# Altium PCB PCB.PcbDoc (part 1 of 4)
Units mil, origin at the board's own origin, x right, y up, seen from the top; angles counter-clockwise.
Board outline 6311.26 x 4737.49 mil, 2 copper layers (Top Layer, Bottom Layer); 252 components, 238 nets, 1140 pads, 635 vias.
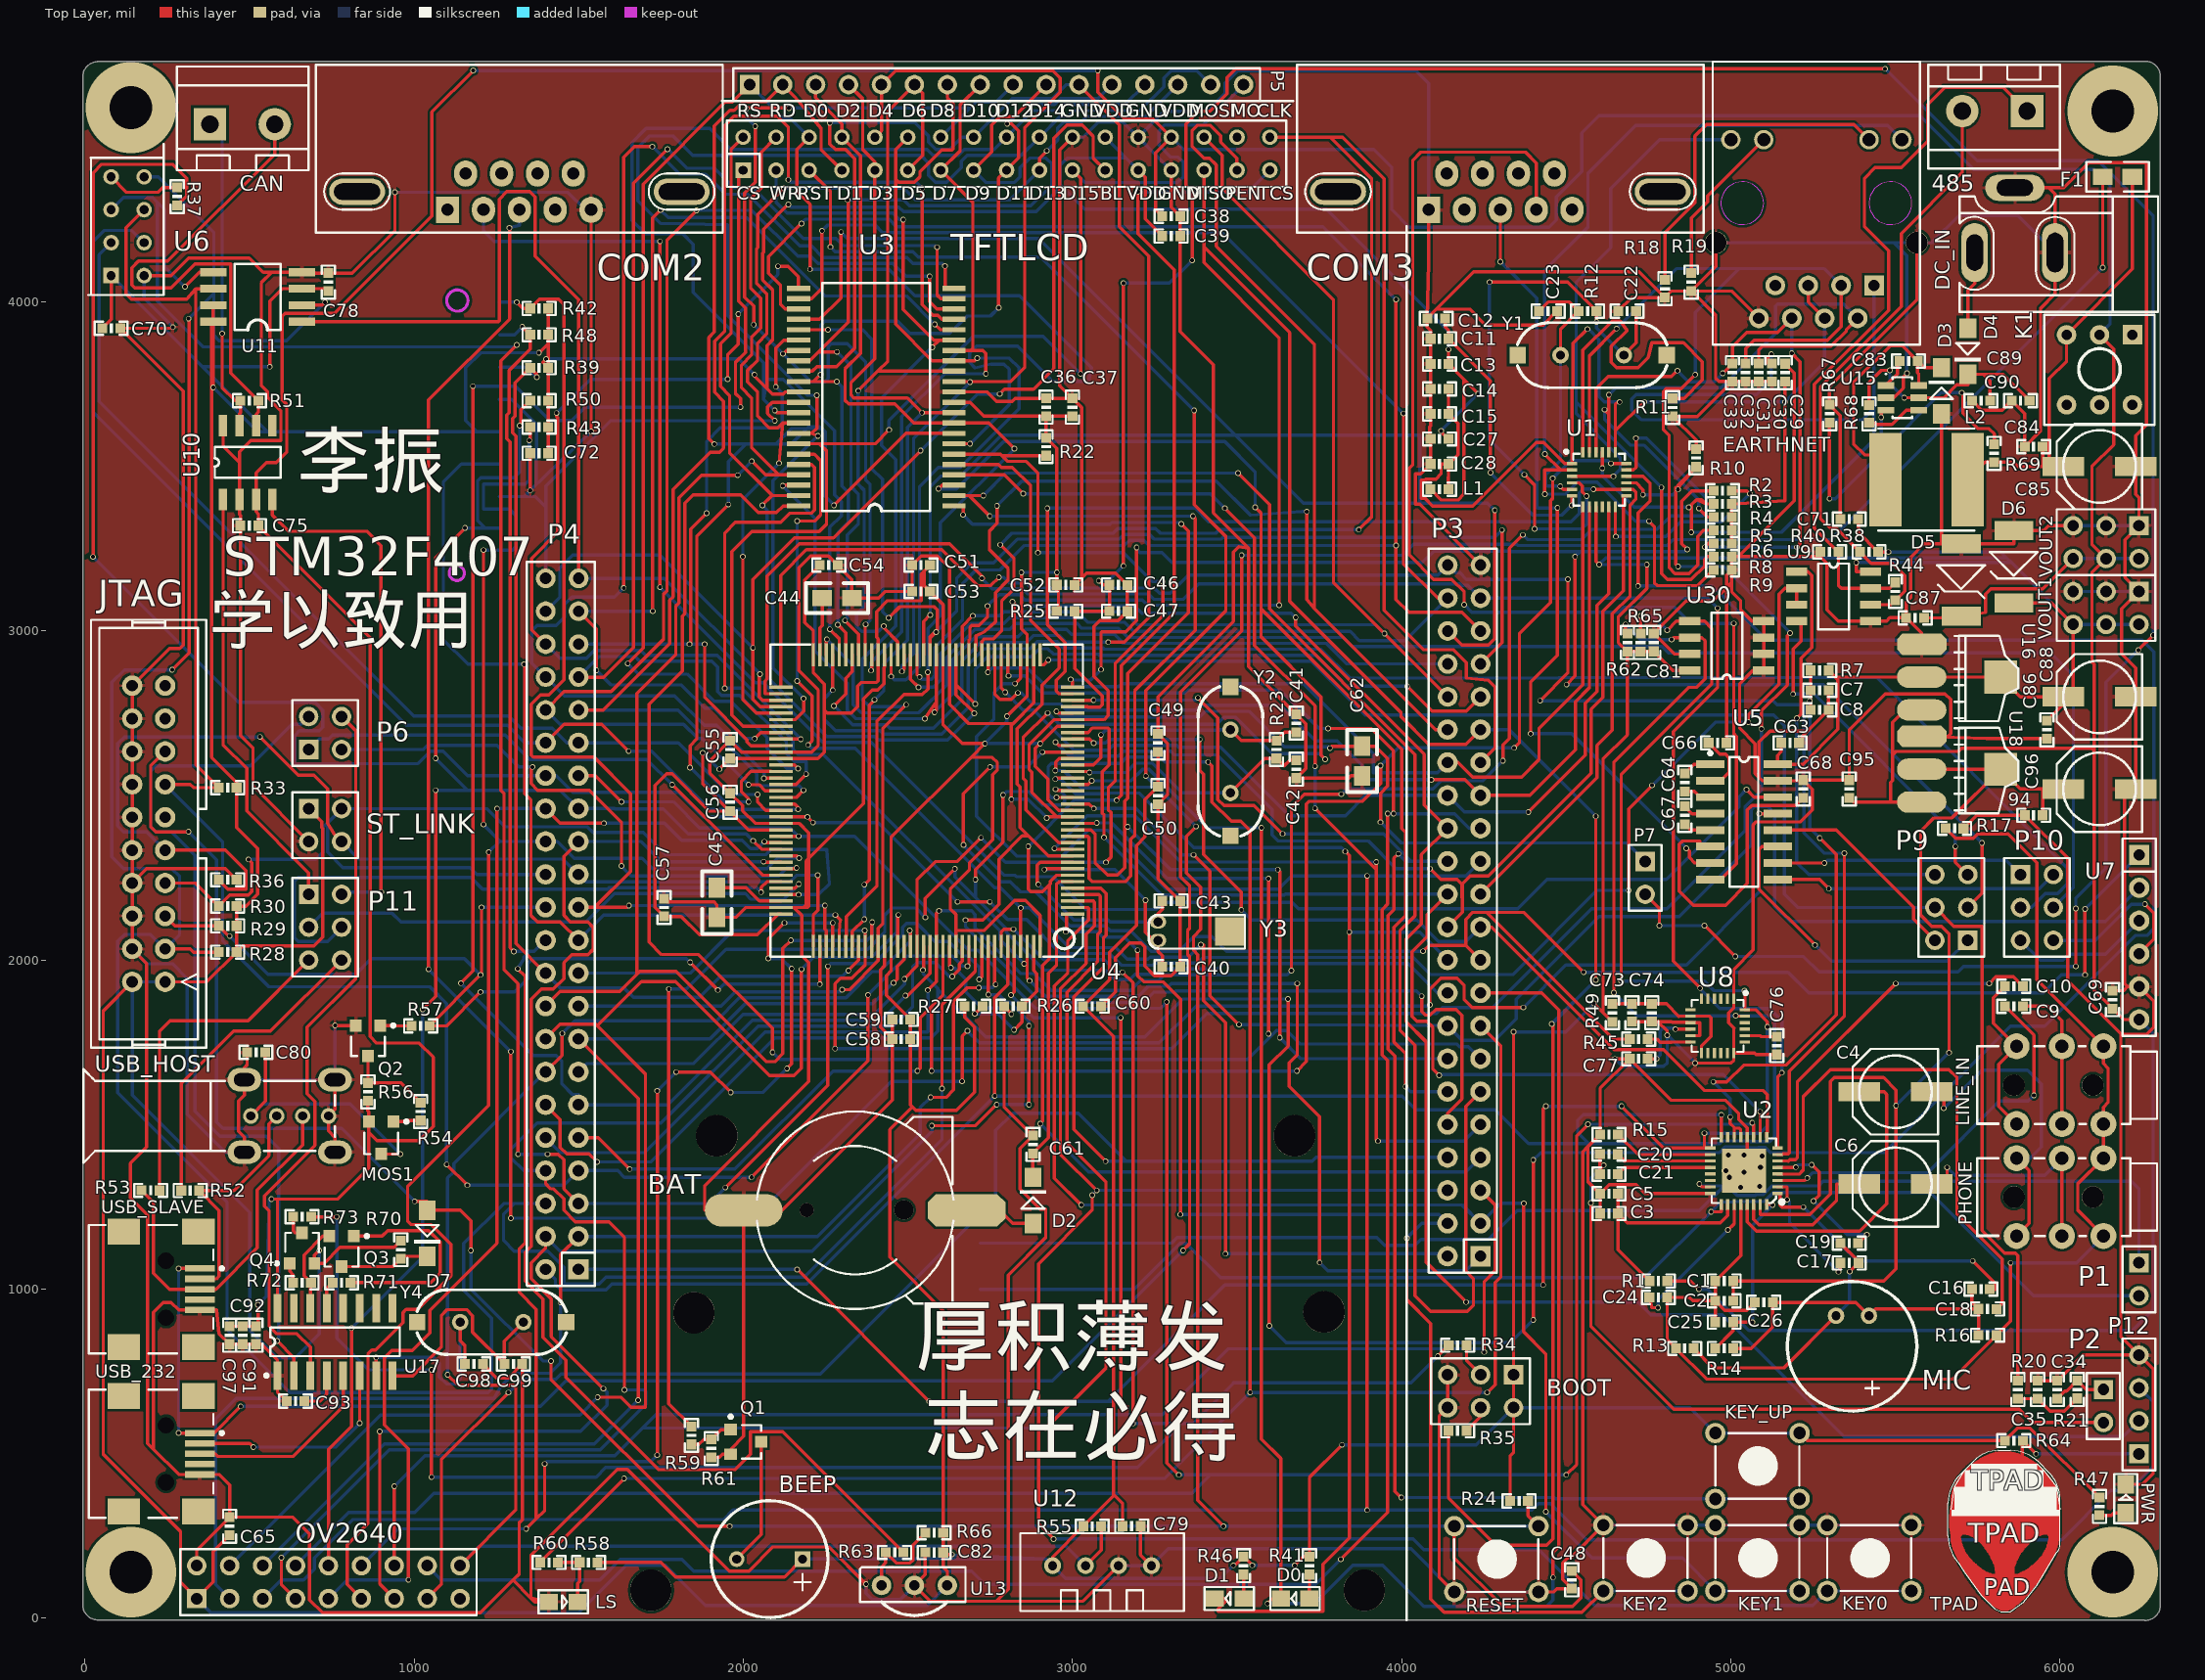
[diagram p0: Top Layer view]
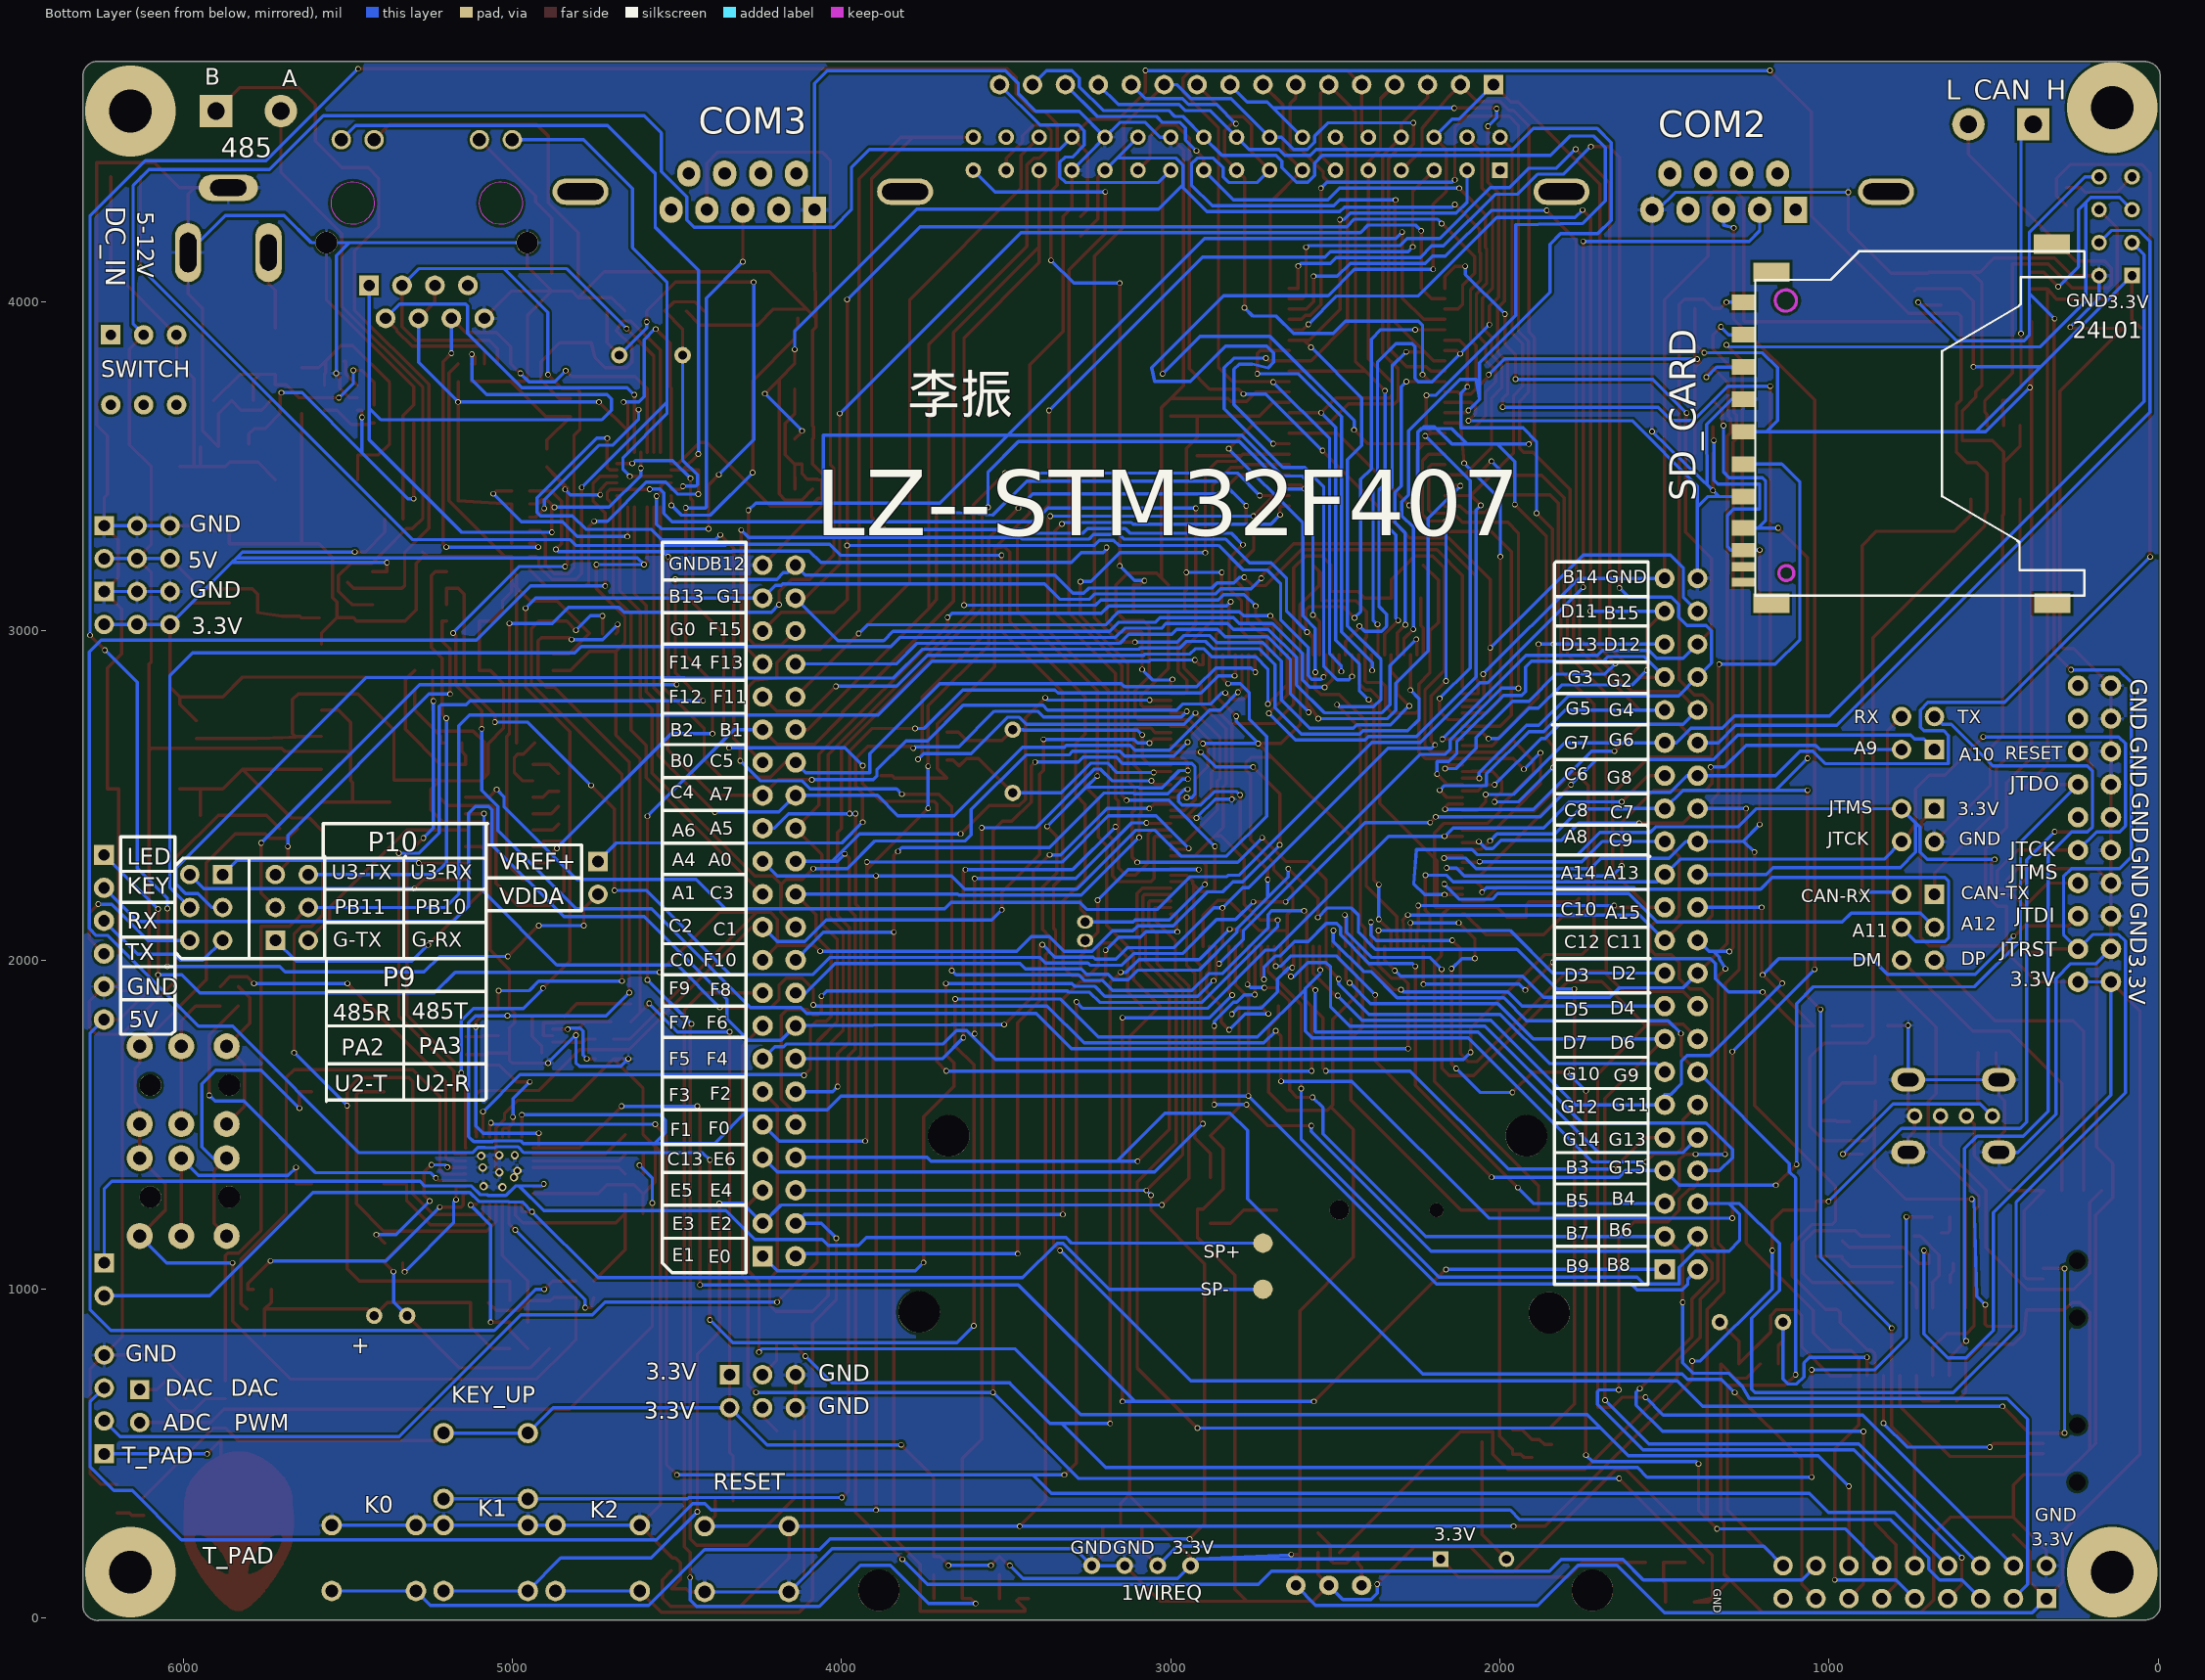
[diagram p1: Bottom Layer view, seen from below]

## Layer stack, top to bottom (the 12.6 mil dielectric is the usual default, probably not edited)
Top Layer: signal copper 1.4
Dielectric: dielectric 12.6, FR-4, Dk 4.8
Bottom Layer: signal copper 1.4

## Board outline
40,-5.01 cw(c40,41.23) -6.25,41.23 -6.25,4683.77 cw(c40,4683.77) 37.89,4729.97 cw(c41.23,4726.23) 41.23,4731.25 6258.77,4731.25 cw(c6258.77,4685) 6305.02,4685 6305.02,40 cw(c6258.77,40) 6258.77,-6.25 cw(c6258.77,-1.23) 6255.48,-5.01

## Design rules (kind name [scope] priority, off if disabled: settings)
Clearance [All] p1: gap=8
FabricationTestpoint [All] p1: side=3 testpointundercomponent=TRUE minsize=40 maxsize=1000 preferedsize=60 minholesize=0 maxholesize=400 preferedholesize=32 testpointgrid=1 allowsidetop=TRUE allowsidebottom=TRUE usegrid=TRUE gridtolerance=0.01
HoleSize [All] p1: absolutevalues=TRUE maxlimit=1000 minlimit=8 maxpercent=80.000 minpercent=20.000
HoleToHoleClearance [All] p1: gap=0 allowstackedmicrovias=TRUE
MinimumSolderMaskSliver [All] p1: minsoldermaskwidth=0
PasteMaskExpansion [All] p1: expansion=10
PlaneClearance [All] p1: clearance=10
PolygonConnect [All] p1: connectstyle=Relief reliefconductorwidth=10 reliefentries=4 polygonreliefangle="90 Angle"
RoutingVias [All] p1: holewidth=12 width=17 viastyle="Through Hole" minholewidth=10 minwidth=17 maxholewidth=1000 maxwidth=1000
SMDNeckDown [All] p1: percent=100.000
SilkToSilkClearance [All] p1: silktosilkclearance=0
SilkscreenOverComponentPads [All] p1: minsilkscreentomaskgap=0
SolderMaskExpansion [All] p1: expansion=10
Width [All] p1: maxlimit=15 minlimit=5 preferedwidth=10
20 further rules are at their usual default settings.

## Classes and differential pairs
component class CPU2: BAT BOOT C36 C37 C38 C39 C40 C41 C42 C43 C44 C45 C46 C47 C48 C49 C50 C51 C52 C53 C54 C55 C56 C57 C58 C59 C60 C61 C62 D2 JTAG P3 P4 P5 P6 P7 R22 R23 R24 R25 R26 R27 R28 R29 R30 R33 R34 R35 R36 RESET ST_LINK TFTLCD U3 U4 Y2 Y3
component class CPU3: BEEP C63 C64 C65 C66 C67 C68 C69 C70 C71 C72 C73 C74 C75 C76 C77 C78 C79 C80 C81 C82 CAN COM2 COM3 D0 D1 KEY0 KEY1 KEY2 KEY_UP LS MOS1 OV2640 P9 P10 P11 P12 PWR Q1 Q2 R37 R38 R39 R40 R41 R42 R43 R44 R45 R46 R47 R48 R49 R50 R51 R52 R53 R54 R55 R56 R57 R58 R59 R60 R61 R62 R63 R64 R65 R66 RS485 SD_CARD TPAD U5 U6 U7 U8 U9 U10 U11 U12 U13 U30 USB_HOST USB_SLAVE
component class PCU1: 94 C1 C2 C3 C4 C5 C6 C7 C8 C9 C10 C11 C12 C13 C14 C15 C16 C17 C18 C19 C20 C21 C22 C23 C24 C25 C26 C27 C28 C29 C30 C31 C32 C33 C34 C35 C83 C84 C85 C86 C87 C88 C89 C90 C91 C92 C93 C95 C96 C97 C98 C99 D3 D4 D5 D6 D7 DC_IN EARTHNET F1 K1 L1 L2 LINE_IN MIC P1 P2 PHONE Q3 Q4 R1 R2 R3 R4 R5 R6 R7 R8 R9 R10 R11 R12 R13 R14 R15 R16 R17 R18 R19 R20 R21 R67 R68 R69 R70 R71 R72 R73 SP+ SP- U1 U2 U15 U16 U17 U18 USB_232 VOUT1 VOUT2 Y1 Y4

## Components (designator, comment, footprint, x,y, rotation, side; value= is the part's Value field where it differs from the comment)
94 "104pF" 0603P 5920,2440 r0 top
485 "RS485" HEAD2L-0.8 5900,4580 r180 top (schematic designator RS485)
BAT "BATT" BATM 2340,1240 r90 top
BEEP "BEEP" BELL-5 2180,180 r180 top
BOOT "BOOT" HDR2X3 4340,740 r180 top
C1 "104pF" 0603P 4980,1025 r0 top
C2 "10uF" 0603P 4980,965 r0 top
C3 "10uF" 0603P 4630,1230 r0 top
C4 "220uF" CC6.56.5 5500,1600 r0 top
C5 "104pF" 0603P 4630,1290 r0 top
C6 "220uF" CC6.56.5 5500,1320 r0 top
C7 "104pF" 0603P 5270,2820 r180 top
C8 "10uF" 0603P 5270,2760 r180 top
C9 "1uF" 0603P 5860,1860 r0 top
C10 "1uF" 0603P 5860,1920 r180 top
C11 "104pF" 0603P 4115,3887.88 r0 top
C12 "10uF" 0603P 4105,3950 r0 top
C13 "104pF" 0603P 4115,3811.75 r0 top
C14 "104pF" 0603P 4115,3735.63 r0 top
C15 "104pF" 0603P 4115,3659.5 r0 top
C16 "1uF" 0603P 5760,1000 r180 top
C17 "1uF" 0603P 5360,1080 r0 top
C18 "1uF" 0603P 5780,940 r180 top
C19 "1uF" 0603P 5360,1140 r180 top
C20 "104pF" 0603P 4630,1410 r180 top
C21 "104pF" 0603P 4630,1350 r180 top
C22 "22pF" 0603P 4685,3972 r0 top
C23 "22pF" 0603P 4445,3972 r180 top
C24 "10uF" 0603P 4780,975 r180 top
C25 "10uF" 0603P 4980,900 r0 top
C26 "221pF" 0603P 5100,960 r0 top
C27 "104pF" 0603P 4115,3583.38 r0 top
C28 "10uF" 0603P 4115,3507.25 r0 top
C29 "223pF" 0603P 5164.94,3785 r270 top
C30 "10pF" 0603P 5124.94,3785 r90 top
C31 "10pF" 0603P 5084.94,3785 r90 top
C32 "10pF" 0603P 5044.94,3785 r90 top
C33 "10pF" 0603P 5004.94,3785 r90 top
C34 "102pF" 0603P 5932,695 r270 top
C35 "101pF" 0603P 5992,695 r270 top
C36 "104pF" 0603P 2920,3680 r270 top
C37 "104pF" 0603P 3000,3680 r270 top
C38 "104pF" 0603P 3300,4260 r0 top
C39 "104pF" 0603P 3300,4200 r0 top
C40 "10pF" 0603P 3300,1980 r0 top
C41 "22pF" 0603P 3680,2720 r270 top
C42 "22pF" 0603P 3680,2580 r90 top
C43 "10pF" 0603P 3300,2180 r0 top
C44 "225pF" 0805 2240,3100 r0 top
C45 "225pF" 0805 1920,2220 r270 top
C46 "10uF" 0603P 3140,3140 r180 top
C47 "104pF" 0603P 3140,3060 r180 top
C48 "104pF" 0603P 4517,117 r90 top
C49 "104" 0603P 3260,2660 r270 top
C50 "104" 0603P 3260,2500 r90 top
C51 "104" 0603P 2540,3200 r0 top
C52 "104" 0603P 2980,3140 r180 top
C53 "104" 0603P 2540,3120 r0 top
C54 "104" 0603P 2260,3200 r180 top
C55 "104" 0603P 1960,2640 r270 top
C56 "104" 0603P 1960,2480 r270 top
C57 "104" 0603P 1760,2160 r270 top
C58 "104" 0603P 2480,1760 r0 top
C59 "104" 0603P 2480,1820 r0 top
C60 "104" 0603P 3060,1860 r180 top
C61 "104pF" 0603P 2880,1440 r270 top
C62 "225pF" 0805 3880,2560 r90 top
C63 "104pF" 0603P 5180,2660 r0 top
C64 "104pF" 0603P 4860,2540 r270 top
C65 "104pF" 0603P 440,280 r90 top
C66 "104pF" 0603P 4960,2660 r180 top
C67 "104pF" 0603P 4860,2440 r90 top
C68 "104pF" 0603P 5220,2520 r270 top
C69 "104pF" 0603P 6160,1880 r270 top
C70 "104pF" 0603P 80,3920 r0 top
C71 "104pF" 0603P 5360,3340 r180 top
C72 "104pF" 0603P 1380,3540 r0 top
C73 "10uF" 0603P 4700,1840 r90 top
C74 "104pF" 0603P 4760,1840 r90 top
C75 "104pF" 0603P 500,3320 r180 top
C76 "10uF" 0603P 5140,1740 r90 top
C77 "104pF" 0603P 4720,1700 r0 top
C78 "104pF" 0603P 740,4060 r90 top
C79 "10pF" 0603P 3180,280 r180 top
C80 "104pF" 0603P 520,1720 r0 top
C81 "104pF" 0603P 4766,2965 r90 top
C82 "104pF" 0603P 2580,200 r0 top
C83 "103pF" 0603P 5540,3820 r0 top
C84 "104pF" 0603P 5920,3560 r0 top
C85 "220uF" CC6.56.5 6120,3500 r0 top
C86 "104pF" 0603P 5960,2700 r90 top
C87 "104pF" 0603P 5560,3040 r180 top
C88 "220uF" CC6.56.5 6120,2800 r0 top
C89 "10uF" 0603P 5760,3700 r0 top
C90 "104pF" 0603P 5880,3700 r0 top
C91 "104pF" 0603P 480,860 r90 top
C92 "10uF" 0603P 520,860 r90 top
C93 "104pF" 0603P 640,660 r0 top
C95 "104pF" 0603P 5360,2520 r270 top
C96 "220uF" CC6.56.5 6120,2520 r0 top
C97 "10uF" 0603P 440,860 r90 top
C98 "22pF" 0603P 1182,773 r180 top
C99 "22pF" 0603P 1302,773 r180 top
CAN "CAN" HEAD2L-0.8 380,4540 r0 top
COM2 "USART_F(母头)" DB9 1320,4280 r0 top
COM3 "USART_M(公头)" DB9 4300,4280 r0 top
D0 "LED0" SMDLED 3720,60 r180 top
D1 "LED1" SMDLED 3520,60 r180 top
D2 "1N4148" DIODE_SOP 2880,1200 r90 top
D3 "SS14" DIODE_SOP 5640,3660 r90 top
D4 "SS14" DIODE_SOP 5720,3920 r270 top
D5 "SMBJ5.0A" SMBJ 5700,3160 r270 top
D6 "SMBJ3.3A" SMBJ 5860,3200 r270 top
D7 "1N4148" DIODE_SOP 1040,1240 r270 top
DC_IN "POWER" DC10B 6160,4320 r180 top
EARTHNET "RJ45" HR911105A 5260,4300 r0 top
F1 "1000mA" 0805 6220,4380 r180 top
JTAG "JTAG" JTAG_20 194,2384 r90 top
K1 "BUTTON" BTN8.5*8.5 6220,3900 r270 top
KEY0 "KEY0" KEY_M 5293,283 r0 top
KEY1 "KEY0" KEY_M 4953,283 r0 top
KEY2 "KEY0" KEY_M 4613,283 r0 top
KEY_UP "KEY_UP" KEY_M 4953,563 r0 top
L1 "220R,2.0A,0.05DCR" 0603P 4115,3431 r180 top
L2 "4.7uH" L_SOP74 5720,3460 r180 top
LINE_IN "LINE_IN" PHONE_ST 6000,1620 r0 top
LS "LSENS" SMDLED 1410,50 r0 top
MIC "MIC" MIC 5420,920 r180 top
MOS1 "SI2301" SO-G3/C2.5 900,1460 r180 top
OV2640 "OV2640" HDR2X9 340,60 r0 top (schematic designator P8)
P1 "SPEAKER" HDR1X2 6240,1080 r270 top
P2 "Header" HDR1X2 6132,695 r270 top
P3 "HEAD2*22" HEAD2*22 4240,1100 r90 top
P4 "HEAD2*22" HEAD2*22 1500,1060 r90 top
P5 "HEAD1*16" HDR1X16 2020,4660 r0 top
P6 "USART1" HDR2X2 680,2640 r0 top
P7 "VREF_SEL" HDR1X2 4740,2300 r270 top
P9 "RS232&485" HDR2X3 5720,2060 r90 top
P10 "RS232&GPS" HDR2X3 5880,2260 r270 top
P11 "CAN&USB" HDR2X3 680,2200 r270 top
P12 "Header 4" HDR1X4 6240,500 r90 top
PHONE "PHONE" PHONE_ST 6000,1280 r0 top
PWR "PWR" SMDLED 6200,320 r90 top
Q1 "S8050" SOT-23R 2003,536 r270 top
Q2 "S8050" SOT-23R 860,1760 r180 top
Q3 "S8050" SOT-23R 780,1120 r180 top
Q4 "S8550" SOT-23R 660,1120 r0 top
R1 "0R" 0603P 4780,1025 r0 top
R2 "510R" 0603P 4975,3426 r0 top
R3 "49.9R" 0603P 4975,3386 r0 top
R4 "49.9R" 0603P 4975,3346 r0 top
R5 "49.9R" 0603P 4975,3306 r0 top
R6 "49.9R" 0603P 4975,3266 r0 top
R7 "10R" 0603P 5270,2880 r180 top
R8 "10K" 0603P 4975,3226 r0 top
R9 "10K" 0603P 4975,3186 r0 top
R10 "10K" 0603P 4895,3526 r270 top
R11 "12.1K" 0603P 4823,3679 r90 top
R12 "1M" 0603P 4565,3972 r180 top
R13 "0R" 0603P 4860,820 r0 top
R14 "680R" 0603P 4980,820 r0 top
R15 "10K" 0603P 4630,1470 r0 top
R16 "47K" 0603P 5780,860 r180 top
R17 "0R" 0603P 5680,2400 r180 top
R18 "510R" 0603P 4800,4040 r90 top
R19 "510R" 0603P 4880,4060 r90 top
R20 "4.7K" 0603P 5872,695 r270 top
R21 "47K" 0603P 6052,695 r90 top
R22 "10K" 0603P 2920,3560 r270 top
R23 "1M" 0603P 3620,2640 r270 top
R24 "10K" 0603P 4357,357 r180 top
R25 "10R" 0603P 2980,3060 r180 top
R26 "0R" 0603P 2820,1860 r180 top
R27 "0R" 0603P 2700,1860 r180 top
R28 "10K" 0603P 434,2024 r180 top
R29 "10K" 0603P 434,2104 r180 top
R30 "10K" 0603P 434,2164 r180 top
R33 "10K" 0603P 434,2524 r180 top
R34 "10K" 0603P 4170,830 r0 top
R35 "10K" 0603P 4170,570 r180 top
R36 "10K" 0603P 434,2244 r180 top
R37 "1K" 0603P 280,4320 r90 top
R38 "360R" 0603P 5420,3240 r180 top
R39 "47K" 0603P 1380,3800 r0 top
R40 "360R" 0603P 5300,3240 r180 top
R41 "510R" 0603P 3720,160 r90 top
R42 "47K" 0603P 1380,3980 r0 top
R43 "47K" 0603P 1380,3620 r0 top
R44 "120R" 0603P 5500,3120 r90 top
R45 "1K" 0603P 4720,1760 r0 top
R46 "510R" 0603P 3520,160 r90 top
R47 "510R" 0603P 6120,340 r90 top
R48 "47K" 0603P 1380,3900 r0 top
R49 "10R" 0603P 4640,1840 r270 top
R50 "47K" 0603P 1380,3700 r0 top
R51 "120R" 0603P 500,3700 r180 top
R52 "10R" 0603P 320,1300 r0 top
R53 "10R" 0603P 200,1300 r180 top
R54 "10K" 0603P 1020,1540 r270 top
R55 "4.7K" 0603P 3060,280 r0 top
R56 "100K" 0603P 860,1600 r270 top
R57 "4.7K" 0603P 1020,1800 r180 top
R58 "47K" 0603P 1530,170 r0 top
R59 "1K" 0603P 1843,556 r270 top
R60 "1K" 0603P 1410,170 r0 top
R61 "10K" 0603P 1903,516 r90 top
R62 "4.7K" 0603P 4686,2965 r270 top
R63 "1K" 0603P 2460,200 r180 top
R64 "1M" 0603P 5860,540 r180 top
R65 "4.7K" 0603P 4726,2965 r270 top
R66 "4.7K" 0603P 2580,260 r0 top
R67 "9.53K" 0603P 5300,3660 r90 top
R68 "100K" 0603P 5420,3660 r270 top
R69 "49.9K" 0603P 5800,3540 r90 top
R70 "10K" 0603P 960,1120 r90 top
R71 "1K" 0603P 780,1020 r0 top
R72 "1K" 0603P 660,1020 r180 top
R73 "1K" 0603P 660,1220 r0 top
RESET "KEY_M" KEY_M 4160,280 r0 top
SD_CARD "sd card" SDCARD_L 1260,3900 r90 bottom
SP+ "SPK+" TP-1.5 2720,1140 r90 top
SP- "SPK-" TP-1.5 2720,1000 r90 top
ST_LINK "ST_LINK" HDR2X2 680,2460 r270 top
TFTLCD "TFT_LCD" db2*17-4.3 2000,4400 r0 top
TPAD "TPAD" ALIENTEK_PAD 5840,280 r0 top
U1 "LAN8720A" QFN24 4600,3460 r0 top
U2 "WM8978" qfn32 5040,1360 r180 top
U3 "IS62WV51216" TSOP44 2640,3380 r180 top
U4 "STM32F407ZET6()STM32F407ZGT6" LQFP144 3000,2140 r180 top
U5 "SP3232" SOP16M 5040,2420 r270 top
U6 "NRF24L01" NRF24L01 180,4080 r0 top
U7 "MODULE" HEAD6 6240,2320 r270 top
U8 "MPU6050" QFN24 4960,1800 r270 top
U9 "SP3485" SOP-8 5200,3180 r0 top
U10 "TJA1050" SOP-8 420,3400 r90 top
U11 "W25Q128" SOIC-8 660,3940 r180 top
U12 "DHT11&DS18B20" DHT11 2940,160 r0 top
U13 "HS0038" HS0038 2420,100 r0 top
U15 "MP2359" SOT-23-6 5471,3746 r0 top
U16 "AMS1117-3.3" AMS1117 5580,2960 r270 top
U17 "CH340G" SOP16M 760,840 r0 top
U18 "AMS1117-3.3" AMS1117 5580,2680 r270 top
U30 "24C02" SOP-8 5100,2880 r180 top
USB_232 "USB" USB/SM0.8-6H5 40,500 r180 top
USB_HOST "USB-A-90" USB-A-90 760,1420 r0 top
USB_SLAVE "USB-B(Mini)" USB/SM0.8-6H5 40,1000 r180 top
VOUT1 "3.3V" HDR2X3 6240,3120 r180 top
VOUT2 "5V" HDR2X3 6240,3320 r180 top
Y1 "25MHz" XTAL_US 4675,3838 r180 top
Y2 "8MHz" XTAL_US 3480,2700 r270 top
Y3 "32.768K" XTAL32 3260,2060 r0 top
Y4 "12MHz" XTAL_US 1140,900 r0 top

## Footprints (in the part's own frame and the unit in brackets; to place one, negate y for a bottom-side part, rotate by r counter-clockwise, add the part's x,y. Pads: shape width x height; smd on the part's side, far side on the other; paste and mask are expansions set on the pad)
0603P [mil]
  rect 30x30 smd: 1(-27,0) 2(27.5,-0.06)
  silkscreen extent -50,-20 50,20
0805 [mil]
  rect 60x50 smd: 1(0,-0.06) 2(90,-0.06)
  silkscreen extent -50,-45 140,45
ALIENTEK_PAD [mil]
  Top Layer drawing of 826 lines, arcs and shapes, not listed
AMS1117 [mil]
  oct 65x150 smd: 1(0.03,-0.06)
  oval 65x150 smd: 2(100.03,-0.06) 3(200.03,-0.06)
  rect 100x100 smd: 4(100.03,239.94)
  silkscreen extent -26,100 234,293
BATM [mm]
  round 1.1 hole 1.1 unplated: 0(0,3.748)
  round 1.5 hole 1.5 unplated: 0(0.025,-3.752)
  oct 2.5x6 smd: 1(0,-8.602)
  oval 2.5x6 smd: 2(0,8.598)
  silkscreen extent -7.62,-7.58 7.62,7.57
BELL-5 [mm]
  rect 1.2x1.2 hole 0.7: 1(0,0)
  round 1.2 hole 0.7: 2(5.08,0)
  silkscreen extent -1.97,-4.51 7.05,4.51
BTN8.5*8.5 [mm]
  rect 1.5x1.5 hole 0.8: 1(0,0)
  round 1.5 hole 0.8: 2(0,-2.54) 3(0,-5.08) 4(5.4,-5.08) 5(5.4,-2.54) 6(5.4,0)
  silkscreen extent -1.55,-6.79 6.95,1.71
CC6.56.5 [mm]
  rect 3.2x1.5 smd: 1(-2.794,0) 2(2.8,0)
  silkscreen extent -3.3,-3.3 3.3,3.3
db2*17-4.3 [mm]
  rect 1.2x1.2 hole 0.7: 1(-0.002,0.006)
  round 1.2 hole 0.7: 2(-0.002,2.546) 3(2.538,0.006) 4(2.538,2.546) 5(5.08,0) 6(5.078,2.546) 7(7.62,0) 8(7.62,2.54) 9(10.158,0.006) 10(10.158,2.546) 11(12.698,0.006) 12(12.698,2.546) 13(15.238,0.006) 14(15.238,2.546) 15(17.778,0.006) 16(17.778,2.546) 17(20.318,0.006) 18(20.318,2.546) 19(22.858,0.006) 20(22.858,2.546) 21(25.398,0.006) 22(25.398,2.546) 23(27.938,0.006) 24(27.938,2.546) 25(30.478,0.006) 26(30.478,2.546) 27(33.018,0.006) 28(33.018,2.546) 29(35.558,0.006) 30(35.558,2.546) 31(38.098,0.006) 32(38.098,2.546) 33(40.638,0.006) 34(40.638,2.546)
  round 3.2 hole 3.2: ""(-7.125,-109.596) ""(-3.81,-88.18) ""(-2.037,-74.525) ""(42.54,-74.525) ""(44.82,-88.12) ""(47.925,-109.596)
  silkscreen extent -1.65,-111.89 51.19,5.33
DB9 [mil]
  oval 170x80 hole 50 slot 140 at 0 deg: 0(-493,55) 0(493,55)
  rect 70x80 hole 38: 1(-218,0)
  oval 70x80 hole 38: 2(-109,0) 3(0,0) 4(109,0) 5(218,0) 6(-163,110) 7(-54,110) 8(55,110) 9(164,110)
  silkscreen extent -618,-70 618,440
DC10B [mil]
  oval 80x180 hole 50 slot 110 at 90 deg: 1(419.09,170)
  oval 80x180 hole 50 slot 120 at 90 deg: 2(175,170)
  oval 180x80 hole 50 slot 110 at 0 deg: 3(297.05,-26.85)
  silkscreen extent -138,0 465,350
DHT11 [mm]
  round 1.3 hole 0.7: 1(0,0) 2(2.54,0) 3(5.08,0) 4(7.62,0)
  silkscreen extent -2.5,-3.5 10.12,2.5
DIODE_SOP [mm]
  rect 1.5x1.3 smd: 1(0,0) 2(3.556,0)
  silkscreen extent 1.14,-1.02 2.56,1.02
HDR1X2 [mm]
  rect 1.5x1.5 hole 0.9: 1(0,0)
  round 1.5 hole 0.9: 2(2.54,0)
  silkscreen extent -1.27,-1.27 3.81,1.27
HDR1X4 [mm]
  rect 1.5x1.5 hole 0.9: 1(0,0)
  round 1.5 hole 0.9: 2(2.54,0) 3(5.08,0) 4(7.62,0)
  silkscreen extent -1.27,-1.27 8.89,1.27
HDR1X16 [mm]
  rect 1.5x1.5 hole 0.9: 1(0,0)
  round 1.5 hole 0.9: 2(2.54,0) 3(5.08,0) 4(7.62,0) 5(10.16,0) 6(12.7,0) 7(15.24,0) 8(17.78,0) 9(20.32,0) 10(22.86,0) 11(25.4,0) 12(27.94,0) 13(30.48,0) 14(33.02,0) 15(35.56,0) 16(38.1,0)
  silkscreen extent -1.27,-1.27 39.37,1.27
HDR2X2 [mm]
  rect 1.5x1.5 hole 0.9: 1(0,0)
  round 1.5 hole 0.9: 2(0,2.54) 3(2.54,0) 4(2.54,2.54)
  silkscreen extent -1.27,-1.27 3.81,3.81
HDR2X3 [mm]
  rect 1.5x1.5 hole 0.9: 1(0,0)
  round 1.5 hole 0.9: 2(0,2.54) 3(2.54,0) 4(2.54,2.54) 5(5.08,0) 6(5.08,2.54)
  silkscreen extent -1.27,-1.27 6.35,3.81
HDR2X9 [mm]
  rect 1.5x1.5 hole 0.9: 1(0,0)
  round 1.5 hole 0.9: 2(0,2.54) 3(2.54,0) 4(2.54,2.54) 5(5.08,0) 6(5.08,2.54) 7(7.62,0) 8(7.62,2.54) 9(10.16,0) 10(10.16,2.54) 11(12.7,0) 12(12.7,2.54) 13(15.24,0) 14(15.24,2.54) 15(17.78,0) 16(17.78,2.54) 17(20.32,0) 18(20.32,2.54)
  silkscreen extent -1.27,-1.27 21.59,3.81
HEAD2*22 [mil]
  rect 62x62 hole 35: 1(0.43,0.42)
  round 62 hole 35: 2(0.43,100.42) 3(100.43,0.42) 4(100.43,100.42) 5(200.43,0.42) 6(200.43,100.42) 7(300.43,0.42) 8(300.43,100.42) 9(400.43,0.42) 10(400.43,100.42) 11(500.43,0.42) 12(500.43,100.42) 13(600.43,0.42) 14(600.43,100.42) 15(700.43,0.42) 16(700.43,100.42) 17(800.43,0.42) 18(800.43,100.42) 19(900.43,0.42) 20(900.43,100.42) 21(1000.43,0.42) 22(1000.43,100.42) 23(1100.43,0.42) 24(1100.43,100.42) 25(1200.43,0.42) 26(1200.43,100.42) 27(1300.43,0.42) 28(1300.43,100.42) 29(1400.43,0.42) 30(1400.43,100.42) 31(1500.43,0.42) 32(1500.43,100.42) 33(1600.43,0.42) 34(1600.43,100.42)
  round 60 hole 35: 35(1700,0) 36(1700,100) 37(1800,0) 38(1800,100) 39(1900,0) 40(1900,100) 41(2000,0) 42(2000,100) 43(2100,0) 44(2100,100)
  silkscreen extent -50,-50 2150,157
HEAD2L-0.8 [mm]
  rect 2.5x2.5 hole 1.35: 1(0,0)
  round 2.5 hole 1.35: 2(5,0)
  silkscreen extent -2.54,-3.56 7.62,4.45
HEAD6 [mil]
  rect 62x62 hole 35: 1(0.42,0.43)
  round 62 hole 35: 2(100.42,0.43) 3(200.42,0.43) 4(300.42,0.43) 5(400.42,0.43) 6(500.42,0.43)
  silkscreen extent -50,-50 550,51
HR911105A [mil]
  rect 60x60 hole 35: 1(175.2,-250)
  round 60 hole 35: 2(125.2,-350) 3(75.2,-250) 4(25.2,-350) 5(-24.8,-250) 6(-74.8,-350) 7(-124.8,-250) 8(-174.8,-350)
  round 59.06 hole 40.16: 9(259.84,192.91) 12(-259.84,192.91)
  round 59.05 hole 40.16: 10(160,192.91) 11(-160,192.91)
  round 66.93 hole 64.96: 13(305.12,-120) 14(-305.12,-120)
  Keep-Out Layer circle w2: c225.04,0 r64.96
  Keep-Out Layer circle w2: c-224.96,0 r64.96
  silkscreen extent -315,-430 315,430
HS0038 [mm]
  round 1.5 hole 0.8: 1(0,0) 2(2.54,0) 3(5.08,0)
  silkscreen extent -1.65,-2.32 6.48,1.4
JTAG_20 [mil]
  round 62 hole 35: 1(-450,-50) 2(-450,50) 3(-350,-50) 4(-350,50) 5(-250,-50) 6(-250,50) 7(-150,-50) 8(-150,50) 9(-50,-50) 10(-50,50) 11(50,-50) 12(50,50) 13(150,-50) 14(150,50) 15(250,-50) 16(250,50) 17(350,-50) 18(350,50) 19(450,-50) 20(450,50)
  silkscreen extent -650,-175 650,175
KEY_M [mil]
  round 62 hole 38: 1(0,0) 1(255.91,0) 2(0,-200) 2(255.91,-200)
  silkscreen extent 0,-200 255,0
L_SOP74 [mm]
  rect 2.5x7.2 smd: 1(0,0) 2(6.35,0)
  silkscreen extent -0.51,-3.94 6.89,3.94
LQFP144 [mil]
  rect 70.87x10 smd: 1(-0.35,0.02) 2(-0.35,-19.66) 3(-0.35,-39.35) 4(-0.35,-59.03) 5(-0.35,-78.72) 6(-0.35,-98.4) 7(-0.35,-118.09) 8(-0.35,-137.77) 9(-0.35,-157.46) 10(-0.35,-177.14) 11(-0.35,-196.83) 12(-0.35,-216.51) 13(-0.35,-236.2) 14(-0.35,-255.88) 15(-0.35,-275.57) 16(-0.35,-295.25) 17(-0.35,-314.94) 18(-0.35,-334.62) 19(-0.35,-354.31) 20(-0.35,-373.99) 21(-0.35,-393.68) 22(-0.35,-413.36) 23(-0.35,-433.05) 24(-0.35,-452.73) 25(-0.35,-472.42) 26(-0.35,-492.1) 27(-0.35,-511.79) 28(-0.35,-531.47) 29(-0.35,-551.16) 30(-0.35,-570.84) 31(-0.35,-590.53) 32(-0.35,-610.21) 33(-0.35,-629.9) 34(-0.35,-649.58) 35(-0.35,-669.27) 36(-0.35,-688.95) 73(885.47,-688.95) 74(885.47,-669.27) 75(885.47,-649.58) 76(885.47,-629.9) 77(885.47,-610.21) 78(885.47,-590.53) 79(885.47,-570.84) 80(885.47,-551.16) 81(885.47,-531.47) 82(885.47,-511.79) 83(885.47,-492.1) 84(885.47,-472.42) 85(885.47,-452.73) 86(885.47,-433.05) 87(885.47,-413.36) 88(885.47,-393.68) 89(885.47,-373.99) 90(885.47,-354.31) 91(885.47,-334.62) 92(885.47,-314.94) 93(885.47,-295.25) 94(885.47,-275.57) 95(885.47,-255.88) 96(885.47,-236.2) 97(885.47,-216.51) 98(885.47,-196.83) 99(885.47,-177.14) 100(885.47,-157.46) 101(885.47,-137.77) 102(885.47,-118.09) 103(885.47,-98.4) 104(885.47,-78.72) 105(885.47,-59.03) 106(885.47,-39.35) 107(885.47,-19.66) 108(885.47,0.02)
  rect 10x70.87 smd: 37(98.07,-787.38) 38(117.76,-787.38) 39(137.44,-787.38) 40(157.13,-787.38) 41(176.81,-787.38) 42(196.5,-787.38) 43(216.18,-787.38) 44(235.87,-787.38) 45(255.55,-787.38) 46(275.24,-787.38) 47(294.92,-787.38) 48(314.61,-787.38) 49(334.29,-787.38) 50(353.98,-787.38) 51(373.66,-787.38) 52(393.35,-787.38) 53(413.03,-787.38) 54(432.72,-787.38) 55(452.4,-787.38) 56(472.09,-787.38) 57(491.77,-787.38) 58(511.46,-787.38) 59(531.14,-787.38) 60(550.83,-787.38) 61(570.51,-787.38) 62(590.2,-787.38) 63(609.88,-787.38) 64(629.57,-787.38) 65(649.25,-787.38) 66(668.94,-787.38) 67(688.62,-787.38) 68(708.31,-787.38) 69(727.99,-787.38) 70(747.68,-787.38) 71(767.36,-787.38) 72(787.05,-787.38) 109(787.05,98.45) 110(767.36,98.45) 111(747.68,98.45) 112(727.99,98.45) 113(708.31,98.45) 114(688.62,98.45) 115(668.94,98.45) 116(649.25,98.45) 117(629.57,98.45) 118(609.88,98.45) 119(590.2,98.45) 120(570.51,98.45) 121(550.83,98.45) 122(531.14,98.45) 123(511.46,98.45) 124(491.77,98.45) 125(472.09,98.45) 126(452.4,98.45) 127(432.72,98.45) 128(413.03,98.45) 129(393.35,98.45) 130(373.66,98.45) 131(353.98,98.45) 132(334.29,98.45) 133(314.61,98.45) 134(294.92,98.45) 135(275.24,98.45) 136(255.55,98.45) 137(235.87,98.45) 138(216.18,98.45) 139(196.5,98.45) 140(176.81,98.45) 141(157.13,98.45) 142(137.44,98.45) 143(117.76,98.45) 144(98.07,98.45)
  silkscreen extent -32,-819 917,130
MIC [mil]
  round 50 hole 28: 1(0.42,0.29) 2(100.42,0.29)
  silkscreen extent -145,-104 248,290
NRF24L01 [mm]
  round 1.2 hole 0.7: 1(0,0) 3(0,2.54) 4(-2.54,2.54) 5(0,5.08) 6(-2.54,5.08) 7(0,7.62) 8(-2.54,7.62)
  rect 1.2x1.2 hole 0.7: 2(-2.54,0)
  silkscreen extent -4.32,-1.5 1.5,10.16
PHONE_ST [mm]
  round 1.676 hole 1.676: 0(-3.556,0) 0(2.54,0)
  round 2 hole 1: 1(-3.35,-3) 1(-3.35,3) 2(0.15,-3) 2(0.15,3) 3(3.35,-3) 3(3.35,3)
  silkscreen extent -6.39,-3.01 7.49,3
QFN24 [mm]
  rect 0.8x0.25 smd: 1(-2.101,1.25) 2(-2.101,0.75) 3(-2.101,0.25) 4(-2.101,-0.25) 5(-2.101,-0.75) 6(-2.101,-1.25) 13(2.101,-1.25) 14(2.101,-0.75) 15(2.101,-0.25) 16(2.101,0.25) 17(2.101,0.75) 18(2.101,1.25)
  rect 0.25x0.8 smd: 7(-1.25,-2.101) 8(-0.75,-2.101) 9(-0.25,-2.101) 10(0.25,-2.101) 11(0.75,-2.101) 12(1.25,-2.101) 19(1.25,2.101) 20(0.75,2.101) 21(0.25,2.101) 22(-0.25,2.101) 23(-0.75,2.101) 24(-1.25,2.101)
  silkscreen extent -2.66,-2 2,2.28
qfn32 [mm]
  rect 0.8x0.25 smd: 1(-2.601,1.75) 2(-2.601,1.25) 3(-2.601,0.75) 4(-2.601,0.25) 5(-2.601,-0.25) 6(-2.601,-0.75) 7(-2.601,-1.25) 8(-2.601,-1.75) 17(2.601,-1.75) 18(2.601,-1.25) 19(2.601,-0.75) 20(2.601,-0.25) 21(2.601,0.25) 22(2.601,0.75) 23(2.601,1.25) 24(2.601,1.75)
  rect 0.25x0.8 smd: 9(-1.75,-2.601) 10(-1.25,-2.601) 11(-0.75,-2.601) 12(-0.25,-2.601) 13(0.25,-2.601) 14(0.75,-2.601) 15(1.25,-2.601) 16(1.75,-2.601) 25(1.75,2.601) 26(1.25,2.601) 27(0.75,2.601) 28(0.25,2.601) 29(-0.25,2.601) 30(-0.75,2.601) 31(-1.25,2.601) 32(-1.75,2.601)
  rect 3.4x3.4 smd: 33(0,0)
  silkscreen extent -3.06,-2.49 2.49,2.55
SDCARD_L [mm]
  rect 1.2x1.8 smd: 1(0,0) 2(-2.489,0) 3(-4.983,-0.009) 4(-7.483,-0.009) 5(-9.983,-0.009) 6(-12.483,-0.009) 7(-14.908,-0.009) 9(2.517,-0.009)
  rect 1.1x1.8 smd: 8(-16.612,0)
  rect 0.7x1.8 smd: 10(-17.908,-0.009) 12(-19.101,0)
  rect 1.5x2.8 smd: 11(-20.726,-23.834) 11(-20.726,-2.143) 11(4.826,-2.143) 11(7.01,-23.784)
  Keep-Out Layer circle w0.254: c2.642,-3.26 r0.82
  Keep-Out Layer circle w0.254: c-18.39,-3.3 r0.58
  silkscreen extent -20.13,-26.3 6.44,-0.9
SMBJ [mm]
  rect 1.5x3 smd: 1(-2.667,0) 2(2.921,0)
  silkscreen extent -1.02,-1.85 1.52,1.83
SMDLED [mm]
  rect 1.4x1.27 smd: 1(0.001,-0.002) 2(2.211,-0.002)
  silkscreen extent -0.8,-0.89 3.01,0.89
SO-G3/C2.5 [mm]
  rect 0.9x0.95 smd: 1(-0.95,-1.25) 2(0.95,-1.25) 3(0,1.25)
  silkscreen extent -2.08,-1.37 1.3,1.25
SOIC-8 [mil]
  rect 80x24 smd: 1(0,0) 2(0,-50.06) 3(0,-100.06) 4(0,-150.06) 5(270,-150) 6(270,-100) 7(270,-50) 8(270,0)
  silkscreen extent 65,-175 205,25
SOP16M [mm]
  rect 0.6x2.2 smd: 1(-4.445,-2.6) 2(-3.175,-2.6) 3(-1.905,-2.6) 4(-0.635,-2.6) 5(0.635,-2.6) 6(1.905,-2.6) 7(3.175,-2.6) 8(4.445,-2.6) 9(4.445,2.6) 10(3.175,2.6) 11(1.905,2.6) 12(0.635,2.6) 13(-0.635,2.6) 14(-1.905,2.6) 15(-3.175,2.6) 16(-4.445,2.6)
  silkscreen extent -5.42,-2.72 5,1.1
SOP-8 [mil]
  rect 65x25 smd: 1(0,0) 2(0,-50) 3(0,-100) 4(0,-150) 5(224.41,-150) 6(224.41,-100) 7(224.41,-50) 8(224.41,0)
  silkscreen extent 65,-175 159,25
SOT-23-6 [mil]
  rect 50x20 smd: 1(0,0) 2(0,-37.4) 3(0,-74.8) 4(100,-74.8) 5(100,-37.4) 6(100,0)
  silkscreen extent 0,-99 80,35
SOT-23R [mm]
  rect 0.9x0.95 smd: 1(0.95,-1.048) 2(-0.95,-1.048) 3(0,1.302)
  silkscreen extent -2.07,-1.17 1.3,1.3
TP-1.5 [mm]
  round 1.5 smd far side: 1(0,0)
TSOP44 [mm]
  rect 1.8x0.4 smd: 1(-0.009,0.001) 2(-0.009,-0.799) 3(-0.009,-1.599) 4(-0.009,-2.399) 5(-0.009,-3.199) 6(-0.009,-3.999) 7(-0.009,-4.799) 8(-0.009,-5.599) 9(-0.009,-6.399) 10(-0.009,-7.199) 11(-0.009,-7.999) 12(-0.009,-8.799) 13(-0.009,-9.599) 14(-0.009,-10.399) 15(-0.009,-11.199) 16(-0.009,-11.999) 17(-0.009,-12.799) 18(-0.009,-13.599) 19(-0.009,-14.399) 20(-0.009,-15.199) 21(-0.009,-15.999) 22(-0.009,-16.799) 23(11.991,-16.799) 24(11.991,-15.999) 25(11.991,-15.199) 26(11.991,-14.399) 27(11.991,-13.599) 28(11.991,-12.799) 29(11.991,-11.999) 30(11.991,-11.199) 31(11.991,-10.399) 32(11.991,-9.599) 33(11.991,-8.799) 34(11.991,-7.999) 35(11.991,-7.199) 36(11.991,-6.399) 37(11.991,-5.599) 38(11.991,-4.799) 39(11.991,-3.999) 40(11.991,-3.199) 41(11.991,-2.399) 42(11.991,-1.599) 43(11.991,-0.799) 44(11.991,0.001)
  silkscreen extent 1.83,-17.2 10.16,0.4
USB-A-90 [mm]
  round 1.2 hole 0.7: 1(-6.5,2.7) 2(-4.5,2.7) 3(-2.5,2.7) 4(-0.5,2.7)
  oval 2.6x1.8 hole 1 slot 1.6 at 0 deg: 5(0,-0.1) 6(0,5.5) 7(-7,5.5) 8(-7,-0.1)
  silkscreen extent -19.4,-0.9 0,6.3
USB/SM0.8-6H5 [mm]
  rect 2.3x0.5 smd: 1(-7.85,-1.6) 2(-7.85,-0.8) 3(-7.85,0) 4(-7.85,0.8) 5(-7.85,1.6)
  rect 2.5x2 smd: 6(-7.75,4.45) 7(-1.996,4.45) 8(-7.75,-4.45) 9(-1.996,-4.45)
  round 0.6 hole 1.27 unplated: MH1(-5.25,2.2) MH2(-5.25,-2.2)
  silkscreen extent -9.68,-4.95 0.7,4.95
XTAL32 [mil]
  oval 50x40 hole 28: 1(0,0) 2(0,56)
  rect 92.13x86 smd: ""(220,27)
  silkscreen extent -28,-25 264,77
XTAL_US [mil]
  round 50 hole 28: 1(0,0) 2(192.13,0)
  rect 50x50 smd: ""(-130.32,0) ""(322.44,0)
  silkscreen extent -131,-98 323,98

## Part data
94 C1 C2 C3 C5 C7 C8 C9 C10 C11 C12 C13 C14 C15 C16 C17 C18 C19 C20 C21 C22 C23 C24 C25 C26 C27 C28 C29 C30 C31 C32 C33 C34 C35 C36 C37 C38 C39 C40 C41 C42 C43 C44 C45 C46 C47 C48 C49 C50 C51 C52 C53 C54 C55 C56 C57 C58 C59 C60 C61 C62 C63 C64 C65 C66 C67 C68 C69 C70 C71 C72 C73 C74 C75 C76 C77 C78 C79 C80 C81 C82 C83 C84 C86 C87 C89 C90 C91 C92 C93 C95 C97 C98 C99: library part C
485 CAN: library part HEAD2
BAT: library part BAT
BOOT P9 P10 P11 VOUT1 VOUT2: library part "Header 3X2", "Header, 3-Pin, Dual row"
C4 C6 C85 C88 C96: library part CAP
COM2 COM3: library part DB9
D0 D1 PWR: library part LED2, "Typical RED, GREEN, YELLOW, AMBER GaAs LED"
D2 D3 D4 D7: library part D
D5 D6: library part SMBJ, "TVS"
DC_IN: library part POW
EARTHNET: library part HR911105
F1 R1 R2 R3 R4 R5 R6 R7 R8 R9 R10 R11 R12 R13 R14 R15 R16 R17 R18 R19 R20 R21 R22 R23 R24 R25 R26 R27 R28 R29 R30 R33 R34 R35 R36 R37 R38 R39 R40 R41 R42 R43 R44 R45 R46 R47 R48 R49 R50 R51 R52 R53 R54 R55 R56 R57 R58 R59 R60 R61 R62 R63 R64 R65 R66 R67 R68 R69 R70 R71 R72 R73: library part R
KEY0 KEY1 KEY2 KEY_UP: library part KEY_M
L1: library part L
L2: library part L_SOP
LINE_IN PHONE: library part PHONE_M
LS: "LIGHT SENS"
MOS1: library part MOS-P, "IRLML6401/SI2301"
OV2640: library part "Header 9X2", "Header, 9-Pin, Dual row"
P1: library part "Header 2_1", "Header, 2-Pin"
P2 P7: library part "Header 2", "Header, 2-Pin"
P5: library part "Header 16", "Header, 16-Pin"
P6 ST_LINK: library part "Header 2X2", "Header, 2-Pin, Dual row"
P12: "Header, 4-Pin"
Q1 Q2 Q3: library part NPN, "8050/BCW846/BCW847"
Q4: library part PNP, "8550/BCW68"
SP+ SP-: library part TEST-POINT, "测试点"
TPAD: "ALIENTEK TPAD"
U1: library part LAN8720, "ETH PHY"
U2: "24bit ADC&DAC"
U4: library part STM32F407ZET6, "STM32F407ZET6"
U5: library part MAX3232
U7: library part ATK-HC05, "ATK-HC05"
U8: "9轴运动处理传感器"
U9: library part MAX3485
U10: library part SN65HVD230D
U11: library part W25X16, "W25X16;SST25VF016;MX25L1605"
U12: library part DHT11, "数字温湿度传感器"
U15: "DC DC Step Down IC"
U16 U18: library part AMS1117
U17: "USB2UART"
U30: library part 24C256
USB_232 USB_SLAVE: library part USB5
USB_HOST: library part USB_A_90
Y1 Y2 Y4: library part XTAL, "Crystal Oscillator"
Y3: library part XTAL_1, "Crystal Oscillator"

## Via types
v1: diameter 17, hole 12, Top Layer to Bottom Layer, 622 vias
v2: diameter 25, hole 15, Top Layer to Bottom Layer, 9 vias
v3: diameter 275.59, hole 129.92, Top Layer to Bottom Layer, 4 vias

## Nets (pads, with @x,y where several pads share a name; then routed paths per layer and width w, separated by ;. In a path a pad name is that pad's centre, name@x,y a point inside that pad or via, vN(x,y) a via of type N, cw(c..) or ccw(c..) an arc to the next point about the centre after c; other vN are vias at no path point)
1WIRE_DQ: OV2640.18 P4.14 R55.2 U4.124 U12.2 | length 5359
  Top Layer w10: v1(1102,740) 1134,708 1303,708 1309,702 1309,329 OV2640.18@1140,160 ; P4.14@1399.58,1660.43 1450,1710.85 v1(1450,1777) ; v1(2506,2090) 2508.23,2087.77 U4.124@2508.23,2041.55 ; U12.2@3040,160 3087.5,207.5 R55.2@3087.5,279.94
  Bottom Layer w10: v1(1102,740) 1102,1337.86 1120.91,1356.77 1120.91,1381.76 P4.14@1399.58,1660.43 ; OV2640.18@1140,160 1199.03,219.03 2980.97,219.03 U12.2@3040,160 ; v1(1450,1777) 1489,1816 1918.78,1816 1988.28,1885.5 2312.5,1885.5 2392.15,1965.15 2414.57,1965.15 2506,2056.58 v1(2506,2090)
3D_INT: P3.19 R45.1 U4.26 U7.1 | length 5531.9
  Top Layer w10: v1(2669,2350) 2669,2506 v1(2750,2587) ; v1(2909,2632.1) U4.26@3000.35,2632.1 ; v1(4065,2027) 4083,2045 4195,2045 ; v1(4553,1963) 4371,2145 4258,2145 ; R45.1@4693,1760 4643,1760 4258,2145 ; v1(6076,1955) v1(6076,2155.15) ; 4195,2045 P3.19@4239.58,2000.43 4195,2045 ; 4195,2045 4195,2124 4216,2145 ; 4216,2145 4258,2145 ; 4216,2145 4258,2145
  Bottom Layer w10: v1(2669,2350) 2781.23,2237.77 2811.81,2237.77 2842.21,2207.37 2889.06,2207.37 2992.43,2104 3100,2104 3115.16,2088.84 3177.26,2088.84 3239.1,2027 3323.55,2027 3368.05,2071.5 3423.12,2071.5 3467.62,2027 v1(4065,2027) ; v1(2750,2587) 2863.9,2587 v1(2909,2632.1) ; v1(4553,1963) 5174,1963 5237,1900 5949,1900 6004,1955 v1(6076,1955) ; v1(6076,2155.15) U7.1@6240.43,2319.58
AGND: C1.1 C2.1 C24.1 C25.1 C26.1 LINE_IN.3 PHONE.3 R13.1 R16.1 R17.2 U2.28 | length 4094.4
  Top Layer w9.84: 5030.16,1102.16 U2.28@5030.16,1257.59
  Top Layer w10: C25.1@4953,900 C2.1@4953,965 ; 5030.16,1102.16 C1.1@4953,1025 C2.1@4953,965 ; C26.1@5073,960 5049,936 4982,936 C2.1@4953,965 ; R17.2@5652.5,2400.06 5682.88,2369.68 5736.22,2369.68 5749.72,2383.19 5842.81,2383.19 5930,2296 5930,1940 LINE_IN.3@6131.89,1738.11 6131.89,1686.11 6146,1672 6146,1567.11 6131.89,1553 LINE_IN.3@6131.89,1501.89 PHONE.3@6131.89,1398.11 6054,1320.22 6054,1239.78 PHONE.3@6131.89,1161.89 ; v1(5850,1080) 5850,903 R16.1@5807,860 5674,727 4926,727 R13.1@4833,820 4807,846 C24.1@4807,975 4875,975 4885,965 C2.1@4953,965
  Bottom Layer w10: v1(5850,1080) 6050,1080 PHONE.3@6131.89,1161.89
BEEP: P3.18 R59.1 U4.20 | length 4981.6
  Top Layer w10: v1(1774,1912.27) 1774,652 R59.1@1843,583 ; v1(2553,2129.5) 2553,2188 v1(2642.89,2277.89) ; v1(2705.31,2244.59) 2705.31,2275.2 2789,2358.88 v1(2789,2502) ; v1(2949,2519) 2949.5,2519 2953,2515.5 2968.49,2515.5 2970,2513.99 U4.20@3000.35,2513.99
  Bottom Layer w10: v1(1774,1912.27) 1827.41,1912.27 1948.14,2033 2378,2033 2429.75,2084.75 2429.75,2136 2452.25,2158.5 2524,2158.5 v1(2553,2129.5) ; v1(2642.89,2277.89) 2642.89,2252.07 2705.31,2189.64 ; v1(2705.31,2244.59) 2705.31,2189.64 ; v1(2789,2502) 2799,2512 2868,2512 2909,2471 2966,2471 2976,2481 2976,2501 2958,2519 v1(2949,2519) ; P3.18@4139.58,1900.43 4108.57,1900.43 4019.47,1989.53 3457.65,1989.53 3441.12,1973 3272.39,1973 3255.89,1956.5 3190,1956.5 3174.5,1941 3128.89,1941 3100.39,1969.5 2914.55,1969.5 2799.5,2084.55 2799.5,2095.46 ; 2705.31,2189.64 2799.5,2095.46 ; 2705.31,2189.64 2799.5,2095.46
BOOT0: R34.1 R73.2 U4.138 | length 6358.7
  Top Layer w10: R73.2@687.5,1219.94 v1(765.5,1219.94) ; v1(1053,429) v1(1053,755) ; U4.138@2783.82,2041.55 2783.82,2085.82 2792,2094 v1(2821,2094) ; v1(3152,1963) 3184,1931 v1(3184,592) ; v1(4110,797) R34.1@4143,830
  Bottom Layer w10: v1(765.5,1219.94) 765.5,851.5 862,755 v1(1053,755) ; v1(1053,429) 1553,429 1582,458 3198,458 3332,592 ; v1(2821,2094) 2913,2002 3097,2002 3136,1963 v1(3152,1963) ; v1(3184,592) 3332,592 ; 3489.5,715.5 3490,716 4029,716 v1(4110,797) ; 3490,715 3367,592 3332,592
BOOT1: P3.33 R35.2 TFTLCD.29 U4.48 | length 8019.4
  Top Layer w10: U4.48@2685.39,2927.38 2685.39,2972.39 2688.76,2975.76 2688.76,3011.56 2693.78,3016.58 2716.4,3016.58 2742,3042.18 v1(2742,3076) ; v1(3628,3078.5) 3628,3891 3399.92,4119.08 3399.92,4167.08 ; R35.2@4142.5,570.06 4142.5,365.5 4286.23,221.77 4440,221.77 4459.91,241.68 4459.91,1802.09 v1(4456,1806) ; P3.33@4239.58,2700.43 4195,2655.85 4082.68,2655.85 3998.15,2740.38 3998.15,2752.7 3660.5,3090.35 3660.5,3906.5 3399.92,4167.08 ; v1(4590,1940) v1(4590,2437.08) ; 3399.92,4167.08 TFTLCD.29@3399.92,4400.24 3399.92,4167.08
  Bottom Layer w10: v1(2742,3076) 2776.5,3110.5 2839.5,3110.5 2855.5,3094.5 3213.22,3094.5 3229.22,3078.5 v1(3628,3078.5) ; P3.33@4239.58,2700.43 4326.66,2700.43 v1(4590,2437.08) ; v1(4456,1806) v1(4590,1940)
CAN_RX: P11.2 U10.4 | length 1591.4
  Top Layer w10: U10.4@570,3400 570,3352 619,3303 856,3303 900,3259 v1(900,2207)
  Bottom Layer w10: P11.2@780,2200 787,2207 v1(900,2207)
CAN_TX: P11.1 U10.1 | length 1307.7
  Top Layer w10: U10.1@420,3400 420,2654.26 492,2582.26 492,2453 680,2265 P11.1@680,2200
CH340_D+: U17.5 USB_232.3 | length 595.9
  Top Layer w10: USB_232.3@349.06,500 395,500 403,492 633.07,492 785,643.93 U17.5@785,737.64
CH340_D-: U17.6 USB_232.2 | length 665.6
  Top Layer w10: USB_232.2@349.06,531.5 500.5,531.5 v1(512,520) ; v1(835,593) U17.6@835,737.64
  Bottom Layer w10: v1(512,520) 762,520 v1(835,593)
DCMI_D0: OV2640.8 P4.31 U2.11 U4.96 | length 10383.4
  Top Layer w9.84: U2.11@5069.53,1462.41 v1@5069.53,1500.93
  Top Layer w10: P4.31@1499.58,2560.43 1550.57,2560.43 v1(1630,2481) ; U4.96@2114.53,2376.2 v1(2168,2376.2) ; v1(3286.75,1873.25) 3286.75,472.25 v1(3323,436) ; v1(4500,436) 4532,468 4532,1467 v1(4566.14,1501.14) ; v1(5064.96,1505.5) v1@5069.53,1500.93
  Bottom Layer w10: OV2640.8@640,160 801.82,321.82 1001.82,321.82 1060,380 3363,380 3419,436 ; v1(1630,2481) 1787.81,2481 1867.54,2401.27 2142.93,2401.27 v1(2168,2376.2) 2337.8,2376.2 2683.43,2030.57 2711.66,2030.57 2888.73,1853.5 3267,1853.5 v1(3286.75,1873.25) ; v1(3323,436) 3419,436 ; v1(4566.14,1501.14) 5060.6,1501.14 v1(5064.96,1505.5) ; 3419,436 v1(4500,436) 3419,436
DCMI_D1: OV2640.9 P4.30 U4.97 | length 3742.2
  Top Layer w10: v1(983,117) 983,515 910,588 910,792 932,814 995,814 1048,867 1048,936 1252,1140 v1(1252,2460.43) ; P4.30@1399.58,2460.43 1444,2416 v1(1577,2416) ; v1(2064.19,2360) 2067.68,2356.51 U4.97@2114.53,2356.51
  Bottom Layer w10: OV2640.9@740,60 797,117 v1(983,117) ; v1(1252,2460.43) P4.30@1399.58,2460.43 ; v1(1577,2416) 1761,2416 1813,2364 1997,2364 2022.5,2338.5 2042.69,2338.5 v1(2064.19,2360)
DCMI_D2: OV2640.10 P4.29 R50.1 SD_CARD.7 U4.98 | length 5438.9
  Top Layer w10: OV2640.10@740,160 740,513 810,583 v1(810,882) ; v1(1026,1850) 1066,1890 v1(1066,2516) ; v1(1066,2613) 1066,3224 v1(1155.07,3313.07) ; v1(1321,3624) 1325,3628 1325,3672 R50.1@1353,3700 ; v1(2030,2362.5) 2055.67,2336.83 U4.98@2114.53,2336.83
  Bottom Layer w10: v1(810,882) 1026,1098 v1(1026,1850) ; v1(1066,2516) 1163,2516 ; v1(1066,2613) 1163,2516 ; v1(1155.07,3313.07) 1215.93,3313.07 ; v1(1321,3624) 1321,3483.27 1303.55,3465.82 1202.82,3465.82 1193,3456 1193,3336 1215.93,3313.07 ; v1(2030,2362.5) 2009.23,2383.27 1832.53,2383.27 1756.65,2459.15 1610.28,2459.15 1609,2460.43 P4.29@1499.58,2460.43 1444,2516 ; 1163,2516 1444,2516 ; 1163,2516 1444,2516 ; 1215.93,3313.07 SD_CARD.7@1259.64,3313.07 1215.93,3313.07
DCMI_D3: OV2640.11 P4.28 R43.1 SD_CARD.8 U4.99 | length 5427.6
  Top Layer w10: OV2640.11@840,60 797,103 797,224 860,287 860,802.79 872,814.79 882.79,814.79 966,898 966,929 976,939 1010.53,939 1112,1040.47 1112,1136.47 1051.97,1196.5 992,1196.5 980.5,1208 980.5,1312.02 1227,1558.52 v1(1227,2328.43) ; v1(1211,2412) v1(1211,3246) ; v1(1350,3579) 1353,3582 R43.1@1353,3620 ; U4.99@2114.53,2317.14 2162.86,2317.14 v1(2170,2310)
  Bottom Layer w10: v1(1211,2412) 1262.57,2360.43 ; v1(1211,3246) SD_CARD.8@1260,3246 1299,3246 1309,3256 1309,3352 1290,3371 1211,3371 1211,3446 1338,3446 1350,3458 v1(1350,3579) ; v1(1227,2328.43) 1259,2360.43 1262.57,2360.43 ; v1(2170,2310) 2105,2310 2072.5,2277.5 1724.67,2277.5 1692.73,2309.44 1486.56,2309.44 1435.57,2360.43 P4.28@1399.58,2360.43 ; 1262.57,2360.43 P4.28@1399.58,2360.43 ; 1262.57,2360.43 P4.28@1399.58,2360.43
DCMI_D4: OV2640.12 P4.22 R48.1 SD_CARD.1 U4.112 | length 7407.5
  Top Layer w10: v1(1303,2026.3) 1291.5,2037.8 1291.5,3574.31 1281.5,3584.31 1281.5,3656 1289,3663.5 1289,3792 1353,3856 R48.1@1353,3900 v1(1329,3924) ; v1(1315,1973.42) 1337.5,1950.92 1337.5,1140.43 1319.58,1122.5 1319.58,990.42 1371,939 1371,302 ; v1(1397,469) 1397,328 1371,302 ; v1(1739,496) v1(1739,1603) ; v1(1796,1660) 1900,1660 v1(1962,1598) ; v1(2076,2005) 2076,2064 v1(2125,2113) ; v1(2133,1671) 2147,1685 v1(2147,1974) ; U4.112@2272.01,2041.55 v1(2272.01,2113) ; 1371,302 v1(1341,272) 1371,302
  Bottom Layer w10: OV2640.12@840,160 952,272 v1(1341,272) ; SD_CARD.1@1260,3900 1305,3900 v1(1329,3924) ; v1(1303,2026.3) 1352,2026.3 ; v1(1315,1973.42) 1334.11,2004.53 1334.11,2008.41 1352,2026.3 ; v1(1397,469) 1404,476 1719,476 v1(1739,496) ; P4.22@1399.58,2060.43 1365.45,2026.3 ; v1(1739,1603) v1(1796,1660) ; v1(1962,1598) 2060,1598 v1(2133,1671) ; v1(2076,2005) 2116,2005 v1(2147,1974) ; v1(2125,2113) v1(2272.01,2113) ; 1352,2026.3 1365.45,2026.3 ; 1352,2026.3 1365.45,2026.3
DCMI_D5: OV2640.13 P4.4 U4.136 | length 4113.1
  Top Layer w10: v1(896,568) 896,104 OV2640.13@940,60 ; P4.4@1399.58,1160.43 1399.58,1124 1355.58,1080 1355.58,1032 1417,970.58 1417,856 v1(1575,698) ; v1(2573,1497) 2706,1497 v1(2770,1561) ; v1(2744.45,1895) U4.136@2744.45,2041.55 ; v1(2868,1561) v1(2868,1800)
  Bottom Layer w10: v1(896,568) 1506,568 1586,648 1586,687 v1(1575,698) ; P4.4@1399.58,1160.43 1444,1116 2209,1116 2573,1480 v1(2573,1497) ; v1(2744.45,1895) 2777.42,1895 2800,1872.42 2809.42,1872.42 2868,1813.84 v1(2868,1800) ; v1(2770,1561) v1(2868,1561)
DCMI_D6: OV2640.14 P3.5 U4.4 | length 7465.7
  Top Layer w10: OV2640.14@940,160 v1(940,401) ; v1(2919,578) 3102,761 3102,1325 2983.46,1443.54 2983.46,1901.87 3076.5,1994.91 3076.5,2077.68 3084.79,2085.97 3084.79,2193.98 3079.74,2199.03 U4.4@3000.35,2199.03 ; P3.5@4239.58,1300.43 4283.58,1256.43 4283.58,1056.43 4251,1023.85 v1(4251,809)
  Bottom Layer w10: v1(940,401) 1033,494 1610,494 ; v1(2919,578) 1694,578 ; v1(4251,809) 4240.93,819.07 3474.07,819.07 3274,619 1735,619 1694,578 ; 1610,494 1694,578 ; 1610,494 1694,578
DCMI_D7: OV2640.15 P3.8 U4.5 | length 5750.5
  Top Layer w10: OV2640.15@1040,60 1083,103 1083,482 v1(1287,686) ; U4.5@3000.35,2218.72 3086.28,2218.72 3102.79,2202.21 3102.79,2076.26 3094.5,2067.97 3094.5,1979 3004.5,1889 3004.5,1485.5 v1(3101,1389)
  Bottom Layer w10: v1(1287,686) 1327.5,726.5 1430.5,726.5 1446.5,742.5 2234.5,742.5 2767,1275 2767,1482.55 2819.46,1535 3018,1535 3164,1389 ; v1(3101,1389) 3164,1389 ; P3.8@4139.58,1400.43 3740.43,1400.43 3729,1389 ; 3164,1389 3729,1389 ; 3164,1389 3729,1389
DCMI_HREF: OV2640.5 P3.25 P12.3 U4.40 | length 10793.6
  Top Layer w10: v1(2826,2840) 2842.87,2856.87 U4.40@2842.87,2927.38 ; v1(3895,329) v1(3895,2256)
  Bottom Layer w10: OV2640.5@540,60 597,117 664,117 697,150 697,184 813,300 1940,300 1969,329 v1(3895,329) 4396,329 4415.5,348.5 4452.41,348.5 4561.91,239 6005,239 6154.29,388.29 6210.29,388.29 6283,461 6283,657 P12.3@6240,700 ; v1(2826,2840) 2788.5,2840 2761.5,2813 2761.5,2732.5 2709,2680 2709,2437 2830,2316 2969.5,2316 3048,2394.5 3107.5,2394.5 3286,2216 3626,2216 3666,2256 v1(3895,2256) ; P3.25@4239.58,2300.43 4195.15,2256 ; v1(3895,2256) 4195.15,2256 ; v1(3895,2256) 4195.15,2256
DCMI_PCLK: OV2640.16 P3.27 U4.42 | length 7232.1
  Top Layer w10: U4.42@2803.5,2927.38 2803.5,2866.5 v1(2806,2864) ; v1(3777,2704) 3907.04,2704 3975.5,2635.54 v1(3975.5,2445) ; v1(3815.11,179.19) 3957,321.08 3957,1695.63 3941.09,1711.53 3941.09,2153.81 3957.5,2170.21 v1(3957.5,2445)
  Bottom Layer w10: OV2640.16@1040,160 1083,117 1564.76,117 1626.95,179.19 1813.48,179.19 1849.67,143 2694,143 2733.59,103.41 3739.33,103.41 v1(3815.11,179.19) ; v1(2806,2864) 2856,2864 2908.5,2811.5 3342.5,2811.5 3351.63,2820.63 3631.82,2820.63 3748.44,2704 v1(3777,2704) ; v1(3957.5,2445) v1(3975.5,2445) ; P3.27@4239.58,2400.43 4205.57,2400.43 4161,2445 ; v1(3975.5,2445) 4161,2445 ; v1(3975.5,2445) 4161,2445
DCMI_RESET: OV2640.7 P4.8 U4.132 | length 4294.7
  Top Layer w10: v1(597,184) 597,103 OV2640.7@640,60 ; P4.8@1399.58,1360.43 1399.58,1321.42 1416,1305 1424.89,1305 1455,1274.89 1455,1240 1490,1205 1592,1205 1639,1158 v1(1639,694) ; v1(2635,1950) 2656.58,1971.58 2656.58,1987.58 2665.71,1996.71 U4.132@2665.71,2041.55
  Bottom Layer w10: v1(597,184) 925,512 1566,512 1704,650 1704,689 1699,694 v1(1639,694) ; P4.8@1399.58,1360.43 1333.57,1360.43 1294,1400 1294,1424.54 1374.46,1505 1750,1505 1774.5,1529.5 1775,1529.5 2045,1799.5 2456.51,1799.5 2514.5,1857.49 2514.5,1979 2528.5,1993 2583.78,1993 2626.78,1950 v1(2635,1950)
DCMI_SCL: OV2640.4 P4.16 U4.122 | length 4483
  Top Layer w10: P4.16@1399.58,1760.43 1444.15,1805 1552,1805 ; v1(1558,672) 1628,672 1659,641 1703,641 1703,1654 1556.5,1800.5 ; v1(2177,1972) 2177,1671.49 2154.57,1649.07 2079.93,1649.07 1793.99,1935.01 1691.01,1935.01 1556.5,1800.5 ; U4.122@2468.86,2041.55 2468.86,2134.86 v1(2471,2137) ; 1552,1805 1556.5,1800.5 ; 1552,1805 1556.5,1800.5
  Bottom Layer w10: OV2640.4@440,160 898,618 1504,618 v1(1558,672) ; v1(2177,1972) 2213.25,2008.25 2390.25,2008.25 2466.5,2084.5 2466.5,2132.5 v1(2471,2137)
DCMI_SDA: OV2640.6 P4.15 U4.123 | length 3673.4
  Top Layer w10: P4.15@1499.58,1760.43 1681,1579 v1(1681,663) ; v1(2456.54,1931) 2468,1942.46 2468,1980.74 2488.54,2001.28 U4.123@2488.54,2041.55
  Bottom Layer w10: OV2640.6@540,160 910,530 1548,530 v1(1681,663) ; P4.15@1499.58,1760.43 1899.21,1760.43 2006.28,1867.5 2393.04,1867.5 v1(2456.54,1931)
